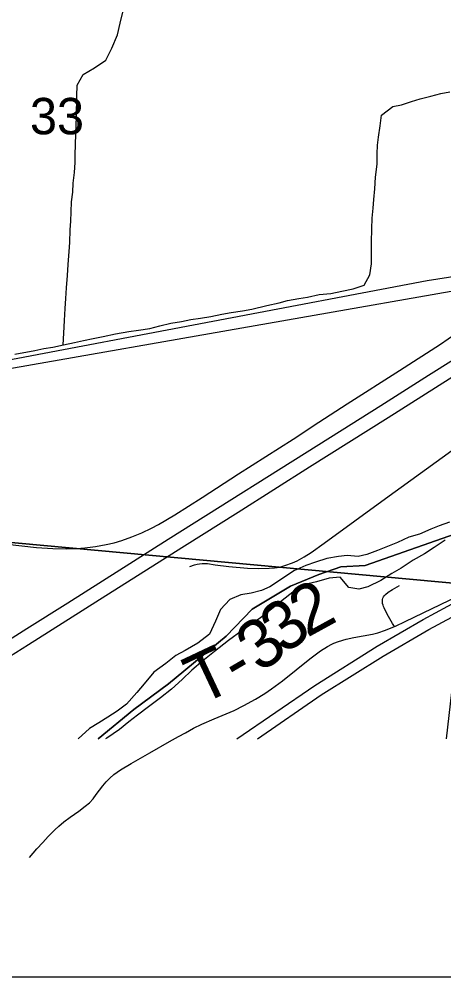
# Model space of a CAD drawing. Extents: x 0 to 34, y 0 to 22.
# Drawn here: x 3.306 to 3.795, y 17.5 to 18.602 of the extents above; entities that cross this region are included whole.
import ezdxf

# ---------------------------------------------------------------- set-up
doc = ezdxf.new("R2010")
doc.units = 0
for name, color, linetype in [('GM_X_Corporation', 7, 'Continuous'), ('GM_X_County_Road', 7, 'Continuous'), ('GM_X_Major_River', 7, 'Continuous'), ('GM_X_Minor_River', 7, 'Continuous'), ('GM_X_Rail_Line', 7, 'Continuous'), ('GM_X_Section_Text', 7, 'Continuous'), ('GM_X_State_Route', 7, 'Continuous'), ('GM_X_Township_Road', 7, 'Continuous'), ('GM_X_Township_Road_Text', 7, 'Continuous'), ('SH_Data', 7, 'Continuous')]:
    doc.layers.add(name, color=color, linetype=linetype)

msp = doc.modelspace()

# ---------------------------------------------------------------- linework, layer by layer
at = {"layer": 'GM_X_Corporation'}
msp.add_lwpolyline([(2.8892, 19.065), (3.9103, 18.9545), (3.8182, 17.9517), (2.7927, 18.046)], close=True, dxfattribs=at)
for points in [[(2.7655, 17.7739), (2.7927, 18.046), (3.8182, 17.9517), (3.798, 17.7739)], [(3.823, 18.0145), (3.7047, 17.9731), (3.6766, 17.9716), (3.6514, 17.9627), (3.6189, 17.9494), (3.5745, 17.9228), (3.5449, 17.8917), (3.4783, 17.837), (3.4384, 17.8074), (3.3975, 17.7739)], [(3.3975, 17.7739), (3.4384, 17.8074), (3.4783, 17.837), (3.5449, 17.8917), (3.5745, 17.9228), (3.6189, 17.9494), (3.6514, 17.9627), (3.6766, 17.9716), (3.7047, 17.9731), (3.823, 18.0145)]]:
    msp.add_lwpolyline(points, dxfattribs=at)
at = {"layer": 'GM_X_County_Road'}
for points in [[(3.2928, 17.9975), (3.3265, 17.994), (3.3451, 17.9928), (3.3606, 17.9924), (3.3729, 17.9927), (3.3822, 17.9933), (3.3945, 17.9949), (3.4066, 17.9971), (3.4157, 17.9992), (3.4246, 18.0018), (3.4362, 18.006), (3.4476, 18.0108), (3.4588, 18.0161), (3.467, 18.0204), (3.4857, 18.0315), (3.5172, 18.0514), (3.5589, 18.0784), (3.6218, 18.1186), (3.6514, 18.1379), (3.6839, 18.1592), (3.7442, 18.1974), (3.7912, 18.2277), (3.8092, 18.2398)], [(3.5028, 17.9719), (3.5084, 17.9739), (3.5113, 17.9747), (3.5142, 17.9752), (3.5172, 17.9755), (3.5201, 17.9755), (3.5231, 17.9753), (3.5322, 17.9738), (3.5477, 17.9721), (3.5694, 17.9702), (3.5817, 17.9697), (3.5941, 17.9699), (3.6002, 17.9704), (3.6063, 17.9714), (3.6122, 17.9731), (3.6209, 17.9761), (3.6265, 17.9786), (3.6346, 17.983), (3.6425, 17.988), (3.6576, 17.9987), (3.7279, 18.0501), (3.8337, 18.1265)]]:
    msp.add_lwpolyline(points, dxfattribs=at)
at = {"layer": 'GM_X_Major_River'}
for points in [[(3.8018, 18.023), (3.7899, 18.0187), (3.7804, 18.0151), (3.7673, 18.009), (3.755, 18.0058), (3.742, 17.9996), (3.7285, 17.9942), (3.7189, 17.9902), (3.7067, 17.9856), (3.6967, 17.9835), (3.6838, 17.9846), (3.6739, 17.9836), (3.6606, 17.9813), (3.6475, 17.977), (3.6364, 17.9731), (3.6226, 17.9669), (3.6083, 17.9573), (3.5948, 17.9485), (3.5852, 17.9445), (3.5733, 17.9414), (3.5615, 17.9393), (3.5488, 17.9339), (3.5383, 17.9224), (3.5323, 17.9092), (3.5255, 17.8941), (3.5123, 17.8838), (3.4977, 17.8753), (3.4869, 17.8695), (3.4753, 17.8606), (3.4614, 17.8506), (3.4504, 17.8372), (3.4418, 17.8271), (3.4301, 17.8137), (3.4193, 17.8056), (3.4085, 17.7986), (3.3981, 17.7923), (3.3876, 17.7857), (3.3744, 17.7739)], [(3.7968, 18.0022), (3.7841, 17.9938), (3.7729, 17.9864), (3.7598, 17.9791), (3.7463, 17.9702), (3.7355, 17.964), (3.7227, 17.9559), (3.7077, 17.9487), (3.6974, 17.9458), (3.6857, 17.948), (3.676, 17.9596), (3.6631, 17.9584), (3.6485, 17.9545), (3.6352, 17.9514), (3.6213, 17.9426), (3.6093, 17.933), (3.5949, 17.9215), (3.5841, 17.913), (3.5729, 17.9049), (3.5632, 17.8982), (3.5474, 17.8868), (3.5311, 17.8742), (3.5179, 17.8635), (3.5051, 17.8527), (3.4939, 17.8419), (3.4818, 17.8308), (3.4691, 17.8208), (3.4555, 17.8105), (3.4427, 17.8009), (3.4327, 17.7935), (3.4218, 17.7846), (3.4072, 17.7746), (3.4059, 17.7739)]]:
    msp.add_lwpolyline(points, dxfattribs=at)
at = {"layer": 'GM_X_Minor_River'}
for points in [[(3.3572, 18.2269), (3.3578, 18.2402), (3.3587, 18.255), (3.3593, 18.2687), (3.3602, 18.2801), (3.3611, 18.2926), (3.362, 18.3066), (3.3629, 18.3192), (3.3642, 18.3343), (3.3648, 18.3446), (3.3653, 18.3594), (3.3658, 18.3692), (3.3663, 18.3799), (3.3669, 18.3916), (3.3681, 18.4026), (3.3686, 18.4129), (3.3703, 18.425), (3.3708, 18.4368), (3.3709, 18.4463), (3.3715, 18.4565), (3.3716, 18.4702), (3.3721, 18.4797), (3.3726, 18.4895), (3.3729, 18.5131), (3.3734, 18.5256), (3.3801, 18.5377), (3.3931, 18.5455), (3.4061, 18.5545), (3.4131, 18.568), (3.4197, 18.5835), (3.4226, 18.5968), (3.4258, 18.6097)], [(3.3016, 18.2162), (3.3245, 18.2205), (3.3348, 18.2227), (3.3454, 18.2244), (3.3576, 18.227), (3.3702, 18.2298), (3.3805, 18.232), (3.3915, 18.2341), (3.4033, 18.2367), (3.4174, 18.2395), (3.4326, 18.2424), (3.444, 18.2438), (3.457, 18.2459), (3.4684, 18.2488), (3.481, 18.2517), (3.4932, 18.2538), (3.5042, 18.2559), (3.5152, 18.2577), (3.527, 18.2595), (3.5396, 18.2624), (3.5503, 18.2641), (3.5636, 18.2662), (3.5742, 18.268), (3.5914, 18.272), (3.6059, 18.2752), (3.6154, 18.2778), (3.6283, 18.2803), (3.6382, 18.2817), (3.6516, 18.2849), (3.6653, 18.2859), (3.6778, 18.2888), (3.6908, 18.2913), (3.7037, 18.2957), (3.71, 18.3074), (3.712, 18.3203), (3.7118, 18.3343), (3.7119, 18.345), (3.7125, 18.3602), (3.7127, 18.3727), (3.7139, 18.3841), (3.7148, 18.3943), (3.7157, 18.4064), (3.7167, 18.4197), (3.7184, 18.4349), (3.7185, 18.4467), (3.719, 18.4565), (3.7199, 18.466), (3.722, 18.4789), (3.7236, 18.491), (3.7367, 18.5011), (3.7466, 18.5029), (3.758, 18.5069), (3.7679, 18.5099), (3.7801, 18.5128), (3.7919, 18.516), (3.8022, 18.5178)]]:
    msp.add_lwpolyline(points, dxfattribs=at)
at = {"layer": 'GM_X_Rail_Line'}
for points in [[(3.8692, 18.3151), (3.7762, 18.3006), (3.2823, 18.2072), (2.7983, 18.1135), (2.3397, 18.0267), (2.0494, 17.9677)], [(2.0494, 17.9624), (3.2848, 18.1978), (3.8715, 18.3004), (3.925, 18.3113)], [(3.5571, 17.7739), (3.6466, 17.8353), (3.7183, 17.8803), (3.7714, 17.9111), (3.814, 17.934), (3.8577, 17.955), (3.9088, 17.9772), (4.0358, 18.0298), (4.165, 18.0831), (4.2819, 18.1313), (4.3768, 18.1699), (4.4059, 18.18), (4.4332, 18.1883), (4.4827, 18.2024), (4.5186, 18.2144), (4.5474, 18.2248), (4.586, 18.241)], [(3.5807, 17.7739), (3.654, 17.8242), (3.7253, 17.8689), (3.778, 17.8995), (3.8201, 17.9222), (3.8633, 17.9429), (3.914, 17.9649), (4.0409, 18.0175), (4.1701, 18.0708), (4.2869, 18.119), (4.5186, 18.2144)]]:
    msp.add_lwpolyline(points, dxfattribs=at)
at = {"layer": 'GM_X_State_Route'}
for points in [[(3.1146, 17.7739), (3.1751, 17.8116), (3.3152, 17.9005), (3.3625, 17.9303), (3.4781, 18.0033), (3.6648, 18.1207), (3.7226, 18.1571), (3.7777, 18.192), (3.8671, 18.2482), (3.9196, 18.2814), (3.9722, 18.3146), (4.0195, 18.3442), (4.1115, 18.4022), (4.143, 18.422), (4.1615, 18.4336), (4.1806, 18.4456), (4.2009, 18.4584), (4.2299, 18.4766), (4.3463, 18.5502), (4.374, 18.5677)], [(3.1448, 17.7739), (3.1523, 17.7785), (3.2294, 17.8269), (3.3171, 17.8823), (3.4064, 17.9385), (3.4967, 17.9957), (3.5584, 18.0343), (3.6406, 18.0865), (3.731, 18.1434), (3.8287, 18.2051), (3.9189, 18.2619), (4.0139, 18.3216), (4.1002, 18.3763), (4.154, 18.41)]]:
    msp.add_lwpolyline(points, dxfattribs=at)
at = {"layer": 'GM_X_Township_Road'}
for points in [[(3.7383, 17.903), (3.7396, 17.9035), (3.7508, 17.9087), (3.8121, 17.9383), (3.8175, 17.9414), (3.8202, 17.9432), (3.8228, 17.9449), (3.8273, 17.949), (3.8324, 17.9523), (3.8377, 17.9554), (3.8432, 17.9581), (3.8603, 17.9656), (3.8924, 17.9792), (3.896, 17.9806), (3.8996, 17.9814), (3.9011, 17.9816), (3.9023, 17.9816), (3.9032, 17.9813)], [(3.7383, 17.903), (3.7363, 17.9065), (3.7301, 17.9173), (3.7266, 17.9244), (3.7259, 17.926), (3.7253, 17.9274), (3.7248, 17.9296), (3.7245, 17.9314), (3.7246, 17.934), (3.725, 17.9356), (3.7257, 17.9372), (3.7265, 17.9383), (3.7279, 17.9399), (3.7312, 17.9424), (3.7361, 17.9456), (3.7443, 17.95)], [(3.3182, 17.6372), (3.3269, 17.6472), (3.3339, 17.6546), (3.3399, 17.6613), (3.3477, 17.6691), (3.3521, 17.6735), (3.3578, 17.6784), (3.365, 17.6836), (3.375, 17.6906), (3.3825, 17.6962), (3.3873, 17.7002), (3.3915, 17.7049), (3.3953, 17.7098), (3.3989, 17.7148), (3.4027, 17.7197), (3.4067, 17.7243), (3.411, 17.7287), (3.4156, 17.7327), (3.4231, 17.7381), (3.4352, 17.7455), (3.4569, 17.7578), (3.4795, 17.7706), (3.4899, 17.7764), (3.4978, 17.7807), (3.5071, 17.786), (3.5168, 17.7906), (3.531, 17.7968), (3.5538, 17.8065), (3.565, 17.812), (3.5786, 17.8195), (3.5892, 17.826), (3.5969, 17.8313), (3.6094, 17.8405), (3.641, 17.8656), (3.6534, 17.8749), (3.6612, 17.88), (3.6662, 17.8828), (3.6686, 17.8838), (3.6741, 17.8859), (3.6827, 17.8884), (3.6918, 17.8904), (3.7133, 17.8942), (3.7194, 17.8958), (3.7282, 17.8989), (3.7383, 17.903)]]:
    msp.add_lwpolyline(points, dxfattribs=at)
at = {"layer": 'SH_Data'}
msp.add_line((2, 17.5), (9, 17.5), dxfattribs=at)

# ---------------------------------------------------------------- texts
at = {"layer": 'GM_X_Section_Text'}
msp.add_text('33', height=0.04186, rotation=0, dxfattribs=at).set_placement((3.3189, 18.4691))
at = {"layer": 'GM_X_Township_Road_Text'}
for s, rotation, p in [('2', 28.7131, (3.6377, 17.8897)), ('3', 37.6033, (3.6121, 17.8698)), ('3', 37.5476, (3.5845, 17.8486)), ('T', 25.222, (3.5148, 17.812)), ('-', 30.2569, (3.558, 17.8326))]:
    msp.add_text(s, height=0.0568, rotation=rotation, dxfattribs=at).set_placement(p)

doc.saveas('drawing.dxf')
